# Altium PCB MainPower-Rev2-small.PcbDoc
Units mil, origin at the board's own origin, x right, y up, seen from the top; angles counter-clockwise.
Board outline 9000 x 9000 mil, 4 copper layers (Top Layer, Internal Plane 1, Internal Plane 2, Bottom Layer); 45 components, 21 nets, 446 pads, 0 vias.
Unrouted connection lines stored in the file: 206.
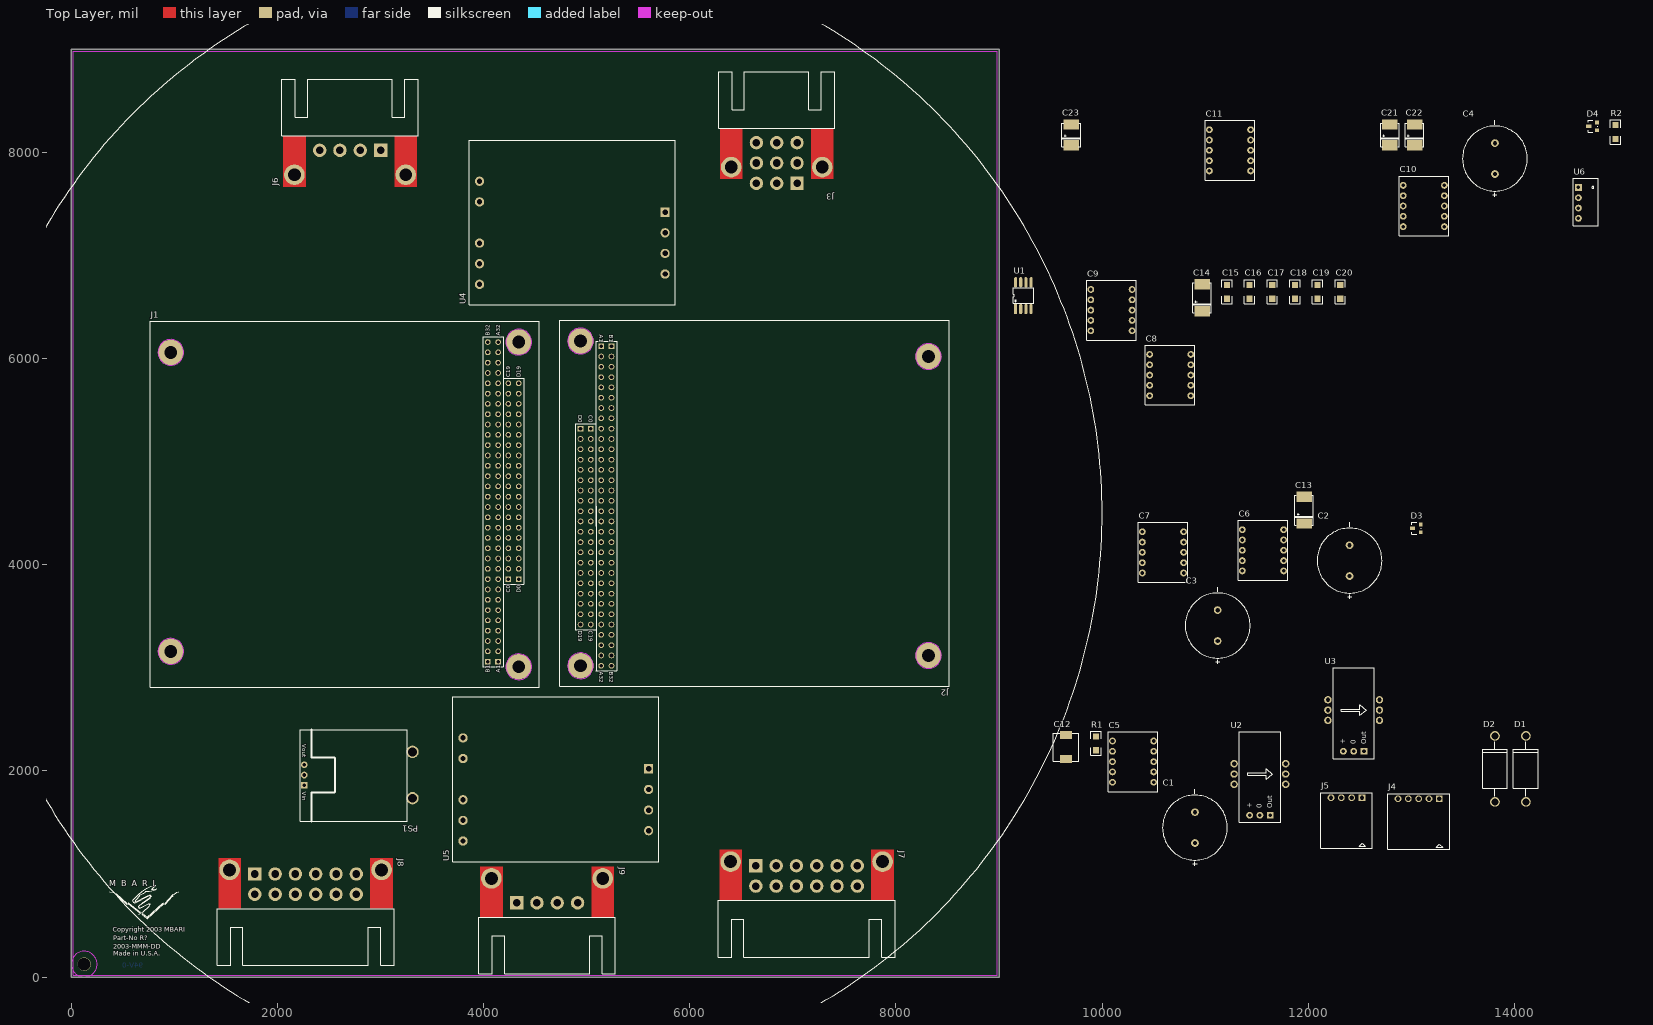
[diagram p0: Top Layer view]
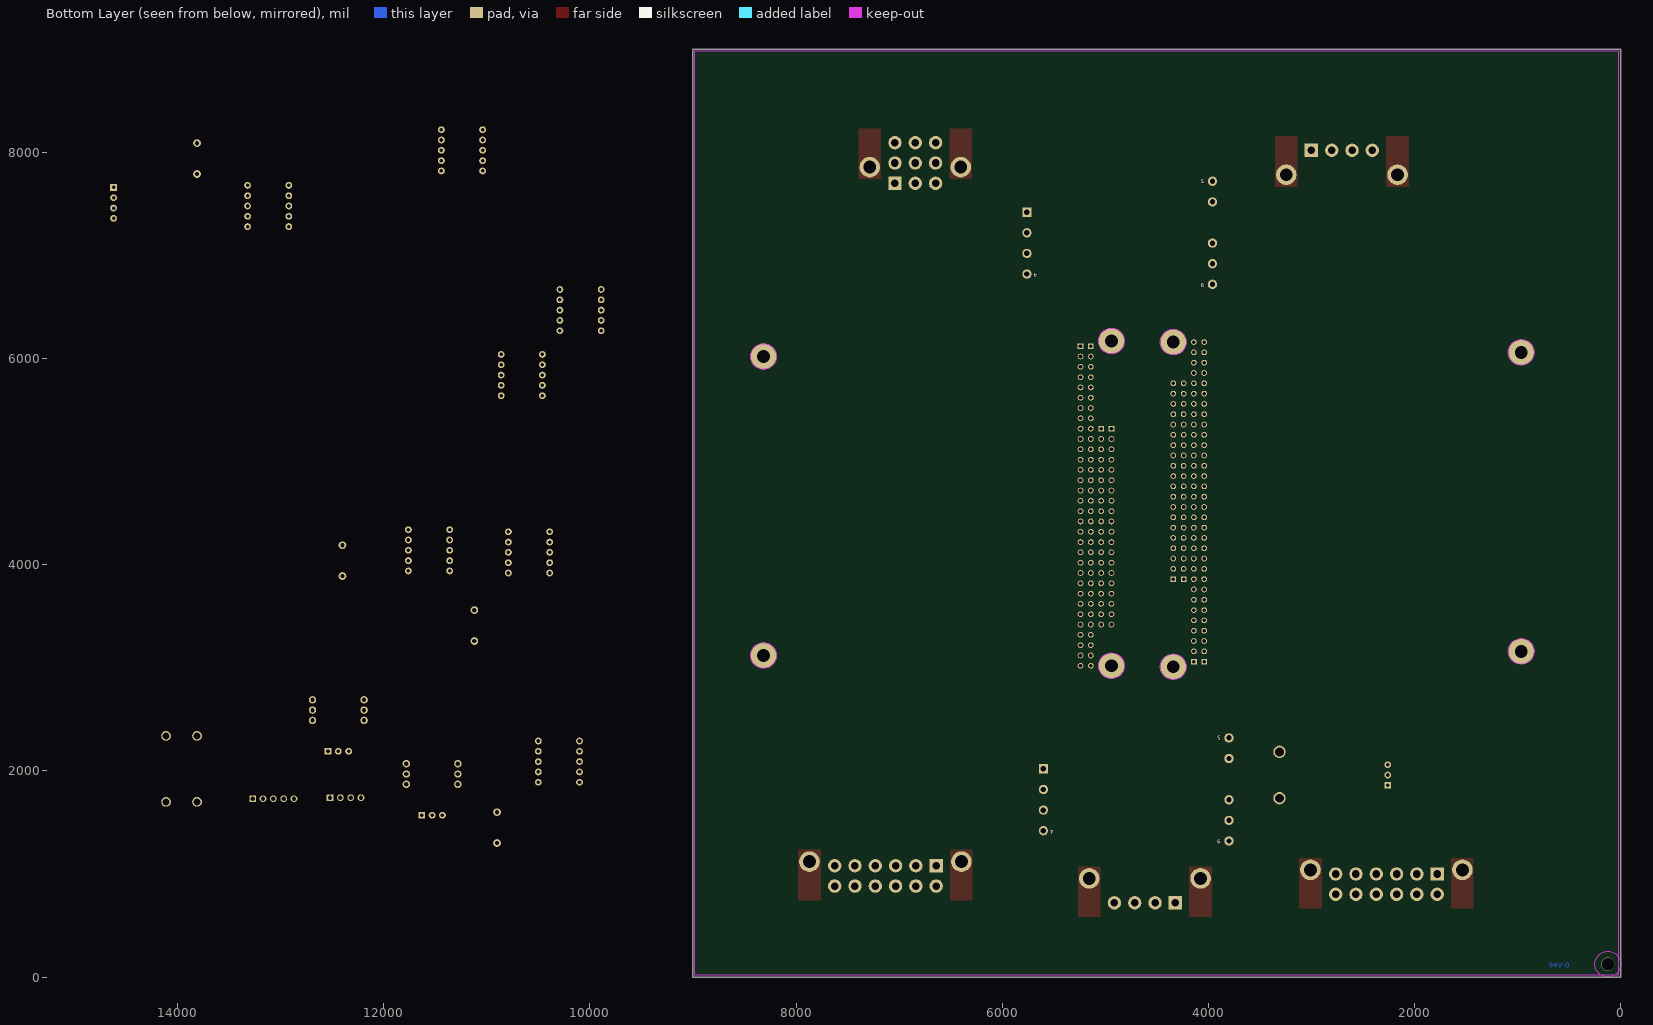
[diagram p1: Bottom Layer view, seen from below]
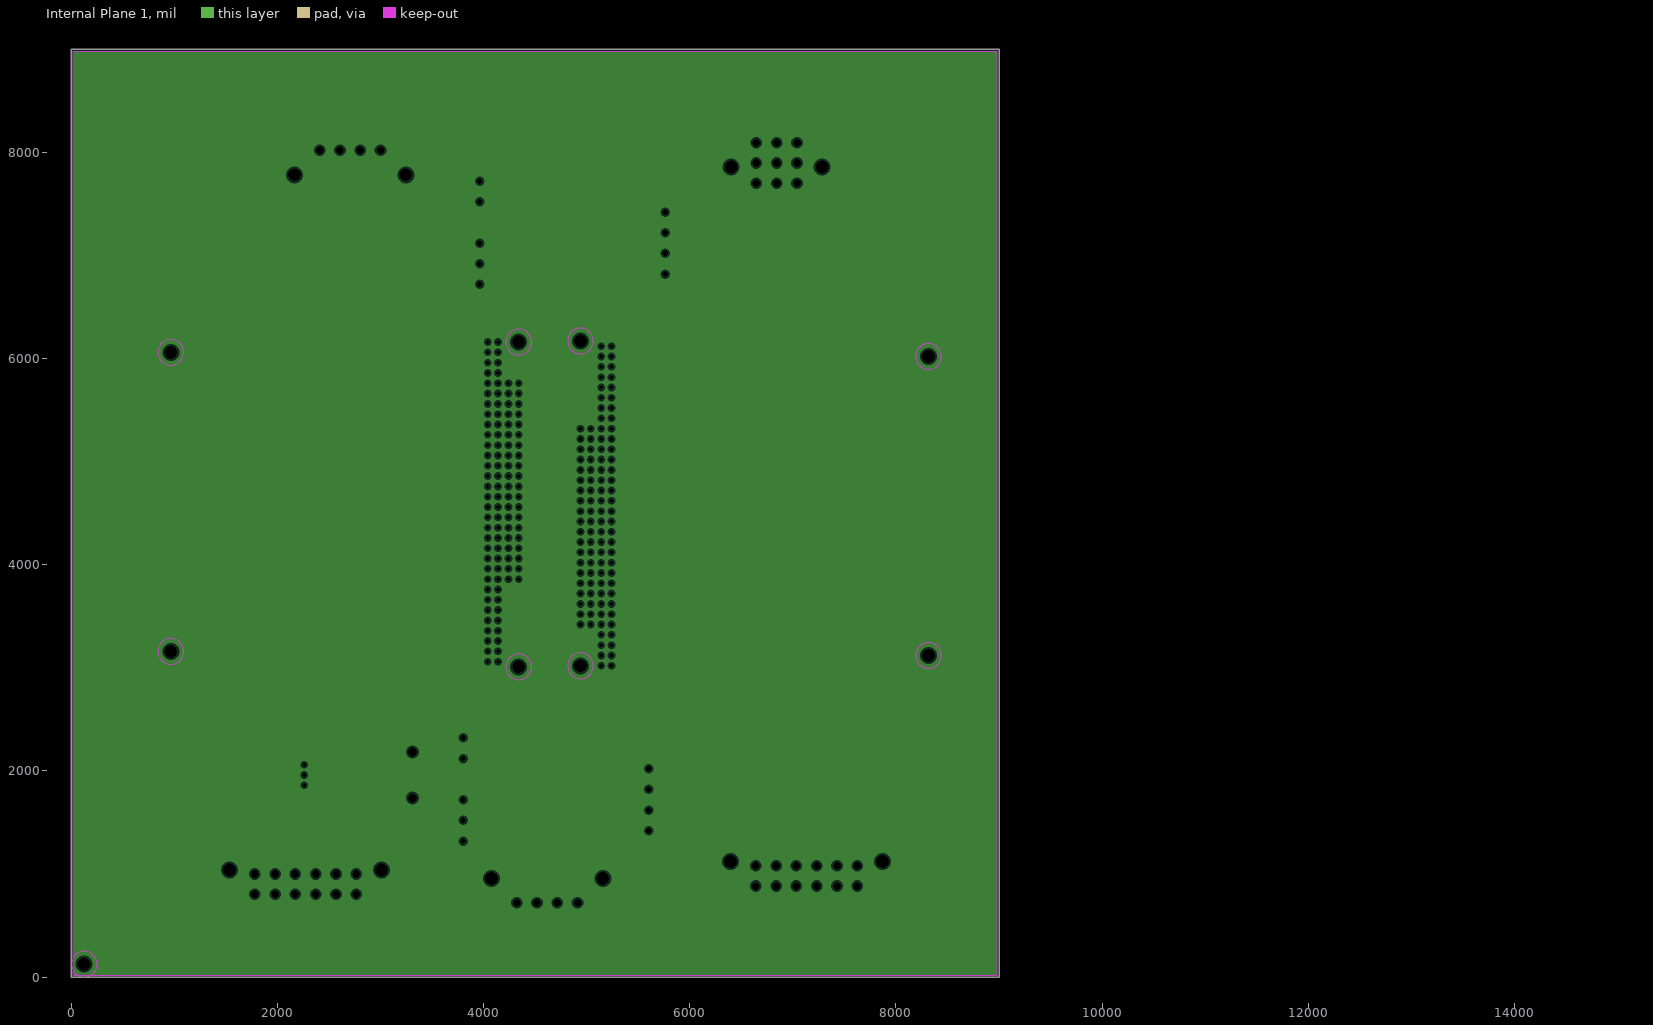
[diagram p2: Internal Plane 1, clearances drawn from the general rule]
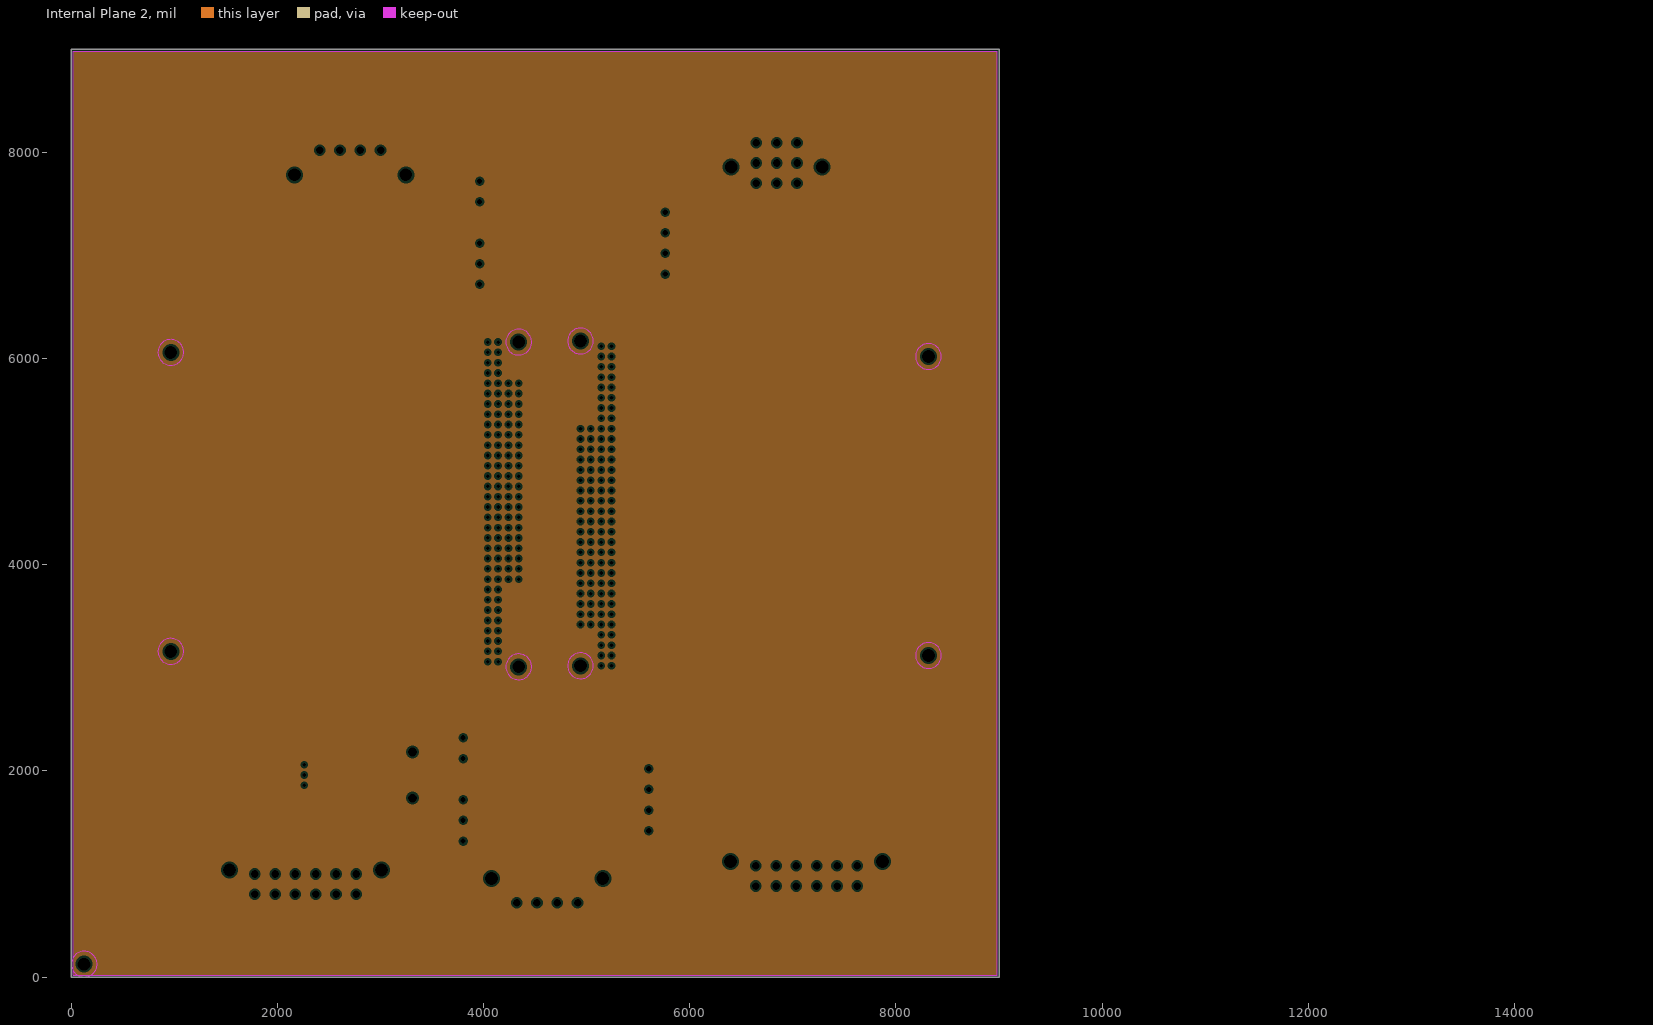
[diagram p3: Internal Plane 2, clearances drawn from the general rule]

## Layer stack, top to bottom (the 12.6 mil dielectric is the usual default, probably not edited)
Top Layer: signal copper 1.4
Dielectric: dielectric 12.6, FR-4, Dk 4.8
Internal Plane 1: plane copper 1.4
Dielectric: dielectric 12.6, FR-4, Dk 4.8
Internal Plane 2: plane copper 1.4
Dielectric: dielectric 12.6, FR-4, Dk 4.8
Bottom Layer: signal copper 1.4

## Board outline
0,0 0,9000 9000,9000 9000,0

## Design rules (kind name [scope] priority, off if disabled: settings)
Clearance [All] p1: gap=13
ComponentClearance [All] p1: gap=10 collisioncheckmode=0
FanoutControl Fanout_Small [(CompPinCount < 5)] p1: bgadir=Out bgaviamode=Centered fanoutstyle=Auto fanoutdirection=OutThenIn viagrid=1 // Fanout_Small (Default Rule)
FanoutControl Fanout_Default [All] p2: bgadir=Out bgaviamode=Centered fanoutstyle=Auto fanoutdirection=Alternating viagrid=1 // Fanout_Default (Default Rule)
FanoutControl Fanout_BGA [IsBGA] p4: bgadir=Out bgaviamode=Centered fanoutstyle=Auto fanoutdirection=Alternating viagrid=1 // Fanout_BGA (Default Rule)
FanoutControl Fanout_LCC [IsLCC] p5: bgadir=Out bgaviamode=Centered fanoutstyle=Auto fanoutdirection=Alternating viagrid=1 // Fanout_LCC (Default Rule)
HoleSize [All] p1: absolutevalues=TRUE maxlimit=152 minlimit=1 maxpercent=80.000 minpercent=20.000
PlaneClearance [All] p1: clearance=20
PlaneConnect [All] p1: planeconnectstyle=Relief reliefexpansion=20 reliefentries=4 reliefconductorwidth=10 reliefairgap=10
PolygonConnect [All] p1: connectstyle=Relief reliefconductorwidth=10 reliefentries=4 polygonreliefangle="90 Angle"
RoutingLayers [All] p1: top layer=Horizontal bottom layer=Vertical
RoutingVias [All] p1: holewidth=35 width=52 viastyle="Through Hole" minholewidth=28 minwidth=32 maxholewidth=86 maxwidth=72
SolderMaskExpansion [All] p1: expansion=4
TestPointUsage [All] p1: valid=0 allowmultiple=FALSE
Testpoint [All] p1: side=15 testpointundercomponent=TRUE minsize=40 maxsize=100 preferedsize=60 minholesize=0 maxholesize=40 preferedholesize=32 testpointgrid=1 style=1023 order=1234567890
Width [All] p1: maxlimit=250 minlimit=8 preferedwidth=12 toplayer_prefwidth=10 bottomlayer_prefwidth=10 minimp=50.000000 maximp=50.000000 favimp=50.000000
9 further rules are at their usual default settings.

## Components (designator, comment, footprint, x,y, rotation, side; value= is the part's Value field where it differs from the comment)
C1 "1000uF" RAD0.3L_0.63D 10900,1300 r90 top
C2 "1000uF" RAD0.3L_0.63D 12400,3890 r90 top
C3 "1000uF" RAD0.3L_0.63D 11120,3260 r90 top
C4 "1000uF" RAD0.3L_0.63D 13810,7790 r90 top
C5 "10uF" CAPSTICK-CS4-5 10100,1890 r90 top
C6 "10uF" CAPSTICK-CS4-5 11360,3940 r90 top
C7 "10uF" CAPSTICK-CS4-5 10390,3920 r90 top
C8 "10uF" CAPSTICK-CS4-5 10460,5640 r90 top
C9 "10uF" CAPSTICK-CS4-5 9890,6270 r90 top
C10 "10uF" CAPSTICK-CS4-5 12920,7280 r90 top
C11 "10uF" CAPSTICK-CS4-5 11040,7820 r90 top
C12 "100pF,2kV" ECK 9630,2110 r90 top
C13 "150uF,10V" 7343pol 11960,4400 r90 top
C14 "47uF,16V" 7343pol 10970,6460 r90 top
C15 "0.1uF" 1206 11210,6580 r90 top
C16 "0.1uF" 1206 11430,6580 r90 top
C17 "0.1uF" 1206 11650,6580 r90 top
C18 "0.1uF" 1206 11870,6580 r90 top
C19 "0.1uF" 1206 12090,6580 r90 top
C20 "0.1uF" 1206 12310,6580 r90 top
C21 "33uF,16V" 6032pol 12790,8070 r90 top
C22 "33uF,16V" 6032pol 13030,8070 r90 top
C23 "33uF,16V" 6032pol 9700,8070 r90 top
D1 "1N5365B" DO-201AD 14110,1700 r90 top
D2 "1N5401" DO-201AD 13810,1700 r90 top
D3 "5V LED" SOT-23 13090,4390 r90 top
D4 "12V LED" SOT-23 14800,8290 r90 top
J1 "PC104-CPU" PC104-ABCD 4140,3060 r90 top
J2 "PC104-AUX" PC104-ABCD 5140,6120 r270 top
J3 "Raw Bus In/Out" PLC09-RA 7040,7700 r180 top
J4 "Temp" CGRID5-RA 13270,1730 r0 top
J5 "CurSense" CGRID4-RA 12520,1740 r0 top
J6 "5V Power" PLA04-RA 3000,8020 r180 top
J7 "12V POWER" PLB12-RA 6640,1080 r0 top
J8 "Raw Bus Power" PLB12-RA 1780,1000 r0 top
J9 "Kearfott/ParoSci" PLA04-RA 4320,720 r0 top
PS1 "78ST133HC" PT78ST-HORIZ 2260,1960 r270 top
R1 "3.3K" 1206 9940,2200 r90 top
R2 "10K" 1206 14980,8130 r90 top
U1 "DS1620S" SOIC-8 9160,6480 r90 top
U2 "LTS6-NP" LTS6-NP 11330,1500 r90 top
U3 "LTS6-NP" LTS6-NP 12240,2120 r90 top
U4 "UHE-5/5000-Q12" DATEL-UHE 5760,7420 r180 top
U5 "UHE-12/2500-D24" DATEL-UHE 5600,2020 r180 top
U6 "NKE1209S" NKEDCDC 14620,7660 r0 top

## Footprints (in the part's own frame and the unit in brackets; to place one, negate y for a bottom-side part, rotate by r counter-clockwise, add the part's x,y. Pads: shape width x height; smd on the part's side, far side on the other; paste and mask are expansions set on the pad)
1206 [mil]
  rect 60x60 smd: 1(0,0) 2(135,0)
  silkscreen extent -50,-50 185,50
6032pol [mil]
  rect 100x150 smd: 1(0,0) 2(200,0)
  silkscreen extent -15,-90 215,90
7343pol [mil]
  rect 100x150 smd: 1(0,0) 2(260,0)
  silkscreen extent -15,-90 275,90
CAPSTICK-CS4-5 [mil]
  round 66 hole 35: 1(0,0) 1(100,0) 1(200,0) 1(300,0) 1(400,0) 2(0,-400) 2(100,-400) 2(200,-400) 2(300,-400) 2(400,-400)
  silkscreen extent -90,-440 490,40
CGRID4-RA [mil]
  rect 66x66 hole 42: 1(0,0)
  round 66 hole 42: 2(-100,0) 3(-200,0) 4(-300,0)
  silkscreen extent -400,-490 100,50
CGRID5-RA [mil]
  rect 66x66 hole 42: 1(0,0)
  round 66 hole 42: 2(-100,0) 3(-200,0) 4(-300,0) 5(-400,0)
  silkscreen extent -500,-490 100,50
DATEL-UHE [mil] "Datel UHE 1.6x2.0 DC/DC Converter"
  rect 90x90 hole 52: 1(0,0)
  round 90 hole 52: 2(0,200) 3(0,400) 4(0,600) 5(1800,-300) 6(1800,-100) 7(1800,300) 8(1800,500) 9(1800,700)
  silkscreen extent -100,-700 1900,900
DO-201AD [mil]
  round 95 hole 67: 1(0,0) 2(640,0)
  silkscreen extent 55,-120 585,120
ECK [mm]
  rect 2x3 smd: 1(0.15,-0.5) 2(6.075,-0.475)
  silkscreen extent -0.4,-3.6 6.5,2.7
LTS6-NP [mil]
  round 72 hole 42: 1(370,-450) 2(470,-450) 3(570,-450) 4(570,50) 5(470,50) 6(370,50)
  rect 66x66 hole 35: a(70,-300)
  round 66 hole 35: b(70,-200) c(70,-100)
  silkscreen extent 0,-400 880,0
NKEDCDC [mil]
  rect 66x66 hole 35: 1(0,0)
  round 66 hole 35: 2(0,-100) 3(0,-200) 4(0,-300)
  silkscreen extent -50,-370 190,90
PC104-ABCD [mil] "PC104 Outline and ABCD Rails"
  round 250 hole 125: 0(-50,-200) 0(100,3175) 0(3000,3175) 0(3100,-200)
  rect 55x55 hole 35: A1(0,0) B1(0,100) C0(800,-100) D0(800,-200)
  round 55 hole 35: A2(100,0) A3(200,0) A4(300,0) A5(400,0) A6(500,0) A7(600,0) A8(700,0) A9(800,0) A10(900,0) A11(1000,0) A12(1100,0) A13(1200,0) A14(1300,0) A15(1400,0) A16(1500,0) A17(1600,0) A18(1700,0) A19(1800,0) A20(1900,0) A21(2000,0) A22(2100,0) A23(2200,0) A24(2300,0) A25(2400,0) A26(2500,0) A27(2600,0) A28(2700,0) A29(2800,0) A30(2900,0) A31(3000,0) A32(3100,0) B2(100,100) B3(200,100) B4(300,100) B5(400,100) B6(500,100) B7(600,100) B8(700,100) B9(800,100) B10(900,100) B11(1000,100) B12(1100,100) B13(1200,100) B14(1300,100) B15(1400,100) B16(1500,100) B17(1600,100) B18(1700,100) B19(1800,100) B20(1900,100) B21(2000,100) B22(2100,100) B23(2200,100) B24(2300,100) B25(2400,100) B26(2500,100) B27(2600,100) B28(2700,100) B29(2800,100) B30(2900,100) B31(3000,100) B32(3100,100) C1(900,-100) C2(1000,-100) C3(1100,-100) C4(1200,-100) C5(1300,-100) C6(1400,-100) C7(1500,-100) C8(1600,-100) C9(1700,-100) C10(1800,-100) C11(1900,-100) C12(2000,-100) C13(2100,-100) C14(2200,-100) C15(2300,-100) C16(2400,-100) C17(2500,-100) C18(2600,-100) C19(2700,-100) D1(900,-200) D2(1000,-200) D3(1100,-200) D4(1200,-200) D5(1300,-200) D6(1400,-200) D7(1500,-200) D8(1600,-200) D9(1700,-200) D10(1800,-200) D11(1900,-200) D12(2000,-200) D13(2100,-200) D14(2200,-200) D15(2300,-200) D16(2400,-200) D17(2500,-200) D18(2600,-200) D19(2700,-200)
  Keep-Out Layer circle w10: c3100,-200 r125
  Keep-Out Layer circle w10: c3000,3175 r125
  Keep-Out Layer circle w10: c100,3175 r125
  Keep-Out Layer circle w10: c-50,-200 r125
  silkscreen extent -250,-400 3300,3375
PLA04-RA [mil]
  round 200 hole 125: 0(-244.5,237) 0(835.5,237)
  rect 130x130 hole 73: 1(0,0)
  round 130 hole 73: 2(197,0) 3(394,0) 4(591,0)
  Top Layer region: -354.5,-138 -134.5,-138 -134.5,354 -354.5,354
  Top Layer region: 725.5,-138 945.5,-138 945.5,354 725.5,354
  silkscreen extent -366,-690 959,-140
PLB12-RA [mil]
  round 200 hole 125: 0(-244.5,40) 0(1229.5,40)
  rect 130x130 hole 73: 1(0,0)
  round 130 hole 73: 2(197,0) 3(394,0) 4(591,0) 5(788,0) 6(985,0) 7(0,-197) 8(197,-197) 9(394,-197) 10(591,-197) 11(788,-197) 12(985,-197)
  Top Layer region: -354.5,-335 -134.5,-335 -134.5,157 -354.5,157
  Top Layer region: 1119.5,-335 1339.5,-335 1339.5,157 1119.5,157
  silkscreen extent -366,-887 1352,-337
PLC09-RA [mil]
  round 200 hole 125: 0(-244.5,-157) 0(638.5,-157)
  rect 130x130 hole 73: 1(0,0)
  round 130 hole 73: 2(197,0) 3(394,0) 4(0,-197) 5(197,-197) 6(394,-197) 7(0,-394) 8(197,-394) 9(394,-394)
  Top Layer region: -354.5,-532 -134.5,-532 -134.5,-40 -354.5,-40
  Top Layer region: 528.5,-532 748.5,-532 748.5,-40 528.5,-40
  silkscreen extent -365,-1084 761,-534
PT78ST-HORIZ [mil]
  round 120 hole 86: 0(-225,1050) 0(225,1050)
  rect 65x65 hole 35: 1(100,0)
  round 65 hole 35: 2(0,0) 3(-100,0)
  silkscreen extent -440,-40 450,1000
RAD0.3L_0.63D [mil]
  round 75 hole 42: 1(0,0) 2(300,0)
  silkscreen extent -220,-315 520,315
SOIC-8 [mil]
  rect 100x30 smd: 1(0,0)
  oval 100x30 smd: 2(0,-50) 3(0,-100) 4(0,-150) 5(260,-150) 6(260,-100) 7(260,-50) 8(260,0)
  silkscreen extent 55,-175 205,25
SOT-23 [mil]
  rect 36x36 smd: 1(0,0) 2(-75,0)
  rect 36x50 smd: 3(-37,80)
  silkscreen extent -95,-5 20,85

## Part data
C1 C2 C3 C4: library part "CAPACITOR POL", "Capacitor"
C5 C6 C7 C8 C9 C10 C11 C12 C13 C14 C15 C16 C17 C18 C19 C20 C21 C22 C23: library part CAPACITOR, "Capacitor"
D1: library part ZENER3, "Zener Diode"
D2: library part DIODE_S, "Diode"
D3 D4: library part LED, "LED"
J1 J2: library part PC104-ABCD, "PC104 ABCD Rails"
J3: library part CON3X3, "9 pin connector"
J4: library part CON5, "Connector"
J5 J6 J9: library part CON4, "Connector"
J7 J8: library part CON12-PLB, "Positronic 12 pin connector"
PS1: library part PT78STXXX, "Power Trends Switching Reg"
R1 R2: library part RESISTOR, "Resistor"
U1: library part DS1620, "DallasSemi Digital Thermometer and Thermostat"
U2 U3: "Current Transducer"
U4 U5: library part UHE, "Datel UHE DC->DC Isolated Converter"
U6: library part NKE1209S-BW, "DC->DC Isol Converter 12->9VDC"

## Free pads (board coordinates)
  round 130 hole 125: 0(125,125)

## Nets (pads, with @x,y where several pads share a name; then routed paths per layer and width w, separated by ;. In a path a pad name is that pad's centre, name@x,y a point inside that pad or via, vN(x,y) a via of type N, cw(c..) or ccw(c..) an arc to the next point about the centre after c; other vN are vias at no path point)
5V: C13.1 C15.1 C16.1 C17.1 C18.1 C19.1 C20.1 J1.B3 J1.B29 J1.D16 J2.B3 J2.B29 J2.D16 J6.1 J6.3 R1.1 U4.5 U4.6
9V: C21.1 J9.3 U6.4
9VGND: C21.2 J9.4 U6.3
12V: C14.1 C22.1 C23.1 J7.1 J7.2 J7.3 J7.4 J7.5 J7.6 PS1.1 R2.1 U5.5 U5.6 U6.2
AN0VJ3: J5.4 U2.b U3.b
AN5VJ3: J5.1 U2.c U3.c
BUS+: D1.2 D2.2 J3.1 J3.2 U2.4 U2.5 U2.6 U3.4 U3.5 U3.6
BUS-: C1.2 C2.2 C3.2 C4.2 C5.2 C6.2 C7.2 C8.2 C9.2 C10.2 C11.2 C12.2 D1.1 D2.1 J3.4 J3.5 J3.6 J8.7 J8.8 J8.9 J8.10 J8.11 J8.12 J9.2 U4.2 U5.2
ELEC+: C2.1 C3.1 C4.1 C6.1 C7.1 C8.1 C9.1 C10.1 C11.1 J8.1 J8.2 J8.3 J8.4 J8.5 J8.6 J9.1 U3.1 U3.2 U3.3 U4.1 U5.1
ELECCUR: J5.3 U3.a
GND: C13.2 C14.2 C15.2 C16.2 C17.2 C18.2 C19.2 C20.2 C22.2 C23.2 D3.3 D4.3 J1.A32 J1.B1 J1.B31 J1.B32 J1.C0 J1.D0 J1.D18 J1.D19 J2.A32 J2.B1 J2.B31 J2.B32 J2.C0 J2.D0 J2.D18 J2.D19 J6.2 J6.4 J7.7 J7.8 J7.9 J7.10 J7.11 J7.12 PS1.2 U4.7 U4.8 U5.7 U5.8 U6.1
LOCO+: C1.1 C5.1 J3.3 U2.1 U2.2 U2.3
LOCOCUR: J5.2 U2.a
NetD3_2: D3.2 R1.2
NetD4_2: D4.2 R2.2
NetJ4_1: J4.1 U1.4
NetJ4_2: J4.2 U1.8
NetJ4_3: J4.3 U1.1
NetJ4_4: J4.4 U1.2
NetJ4_5: J4.5 U1.3
SHIELD: C12.1 J3.7 J3.8 J3.9
pads on no net: D3.1 D4.1 J1.0 J1.A1 J1.A2 J1.A3 J1.A4 J1.A5 J1.A6 J1.A7 J1.A8 J1.A9 J1.A10 J1.A11 J1.A12 J1.A13 J1.A14 J1.A15 J1.A16 J1.A17 J1.A18 J1.A19 J1.A20 J1.A21 J1.A22 J1.A23 J1.A24 J1.A25 J1.A26 J1.A27 J1.A28 J1.A29 J1.A30 J1.A31 J1.B2 J1.B4 J1.B5 J1.B6 J1.B7 J1.B8 J1.B9 J1.B10 J1.B11 J1.B12 J1.B13 J1.B14 J1.B15 J1.B16 J1.B17 J1.B18 J1.B19 J1.B20 J1.B21 J1.B22 J1.B23 J1.B24 J1.B25 J1.B26 J1.B27 J1.B28 J1.B30 J1.C1 J1.C2 J1.C3 J1.C4 J1.C5 J1.C6 J1.C7 J1.C8 J1.C9 J1.C10 J1.C11 J1.C12 J1.C13 J1.C14 J1.C15 J1.C16 J1.C17 J1.C18 J1.C19 J1.D1 J1.D2 J1.D3 J1.D4 J1.D5 J1.D6 J1.D7 J1.D8 J1.D9 J1.D10 J1.D11 J1.D12 J1.D13 J1.D14 J1.D15 J1.D17 J2.0 J2.A1 J2.A2 J2.A3 J2.A4 J2.A5 J2.A6 J2.A7 J2.A8 J2.A9 J2.A10 J2.A11 J2.A12 J2.A13 J2.A14 J2.A15 J2.A16 J2.A17 J2.A18 J2.A19 J2.A20 J2.A21 J2.A22 J2.A23 J2.A24 J2.A25 J2.A26 J2.A27 J2.A28 J2.A29 J2.A30 J2.A31 J2.B2 J2.B4 J2.B5 J2.B6 J2.B7 J2.B8 J2.B9 J2.B10 J2.B11 J2.B12 J2.B13 J2.B14 J2.B15 J2.B16 J2.B17 J2.B18 J2.B19 J2.B20 J2.B21 J2.B22 J2.B23 J2.B24 J2.B25 J2.B26 J2.B27 J2.B28 J2.B30 J2.C1 J2.C2 J2.C3 J2.C4 J2.C5 J2.C6 J2.C7 J2.C8 J2.C9 J2.C10 J2.C11 J2.C12 J2.C13 J2.C14 J2.C15 J2.C16 J2.C17 J2.C18 J2.C19 J2.D1 J2.D2 J2.D3 J2.D4 J2.D5 J2.D6 J2.D7 J2.D8 J2.D9 J2.D10 J2.D11 J2.D12 J2.D13 J2.D14 J2.D15 J2.D17 J3.0 J6.0 J7.0 J8.0 J9.0 PS1.0 PS1.3 U1.5 U1.6 U1.7 U4.3 U4.4 U4.9 U5.3 U5.4 U5.9

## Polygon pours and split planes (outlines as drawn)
no net on Internal Plane 1 (split plane): 20.01,20.01 20.01,8979.99 8979.99,8979.99 8979.99,20.01
no net on Internal Plane 2 (split plane): 20.01,20.01 20.01,8979.99 8979.99,8979.99 8979.99,20.01

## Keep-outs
Keep-Out Layer:
  circle w10: c125,125 r125
  lines w10: 20,20 8980,20 8980,8980 20,8980 20,20
  text ".GKO" at 15240,-540 h90

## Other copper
Top Layer:
  text ".GTL" at 15240,-540 h90
Bottom Layer:
  text "94V-0" at 697.07,88.79 h50
  text ".GBL" at 15240,-540 h90

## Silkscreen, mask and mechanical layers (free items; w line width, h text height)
Top Overlay:
  circle w10: c4500,4500 r5500
  lines w10: 373,826 405,824 436,806 537,715 550,719 557,718 671,631 ; 428,808 531,711 ; 536,708 551,712 666,624 ; 653,608 699,635 758,689 761,696 761,706 759,709 753,710 746,710 ; 684,610 731,573 ; 688,617 736,579 888,717 897,721 911,716 990,802 993,797 1022,823 1042,827 ; 760,695 760,703 758,707 753,709 746,710 ; 894,713 909,708 ; 916,712 981,785 ; 984,782 990,791 ; 746,710 739,707 696,687 679,676 656,672 652,677 653,689 691,721 759,768 770,784 766,795 760,797 736,791 700,771 652,743 622,733 618,737 629,752 647,767 669,797 687,807 702,814 715,822 722,833 757,833 780,838 796,844 812,849 829,859 824,855 795,850 778,850 821,889 772,881 733,863 690,835 651,801 623,774 601,749 597,741 596,735 599,728 604,724 612,719 622,720 750,790 760,793 767,793 771,791 773,787 775,782 772,775 764,766 669,701 658,693 654,685 653,679 657,672 664,670 672,672 746,710 ; 737,568 896,713 737,568
  text "M  B  A  R  I" at 370,880 h55
  text "Copyright 2003 MBARI" at 400,440 h45
  text "Part-No R?" at 405,356.68 h45
  text "2003-MMM-DD" at 405,276.68 h45
  text "Made in U.S.A." at 405,206.68 h45
  text ".GTO" at 15240,-540 h90
Bottom Overlay:
  text ".GBO" at 15250,-540 h90
Top Solder:
  text ".GTS" at 15240,-540 h90
Bottom Solder:
  text ".GBS" at 15240,-540 h90
Drill Guide:
  text ".GG1" at 15450,-540 h90
Mechanical 4:
  the board outline again, w10
Mechanical 16:
  lines w5: -800,1750 -600,1750 ; -800,4500 -600,4500 ; -800,7250 -600,7250 ; 2035,-800 2035,-600 ; 2035,9600 2035,9795 ; 4865,-800 4865,-600 ; 4865,9600 4865,9795 ; 7700,-800 7700,-600 ; 7700,9600 7700,9795 ; 9700,0 15600,0 ; 10530,-800 10530,-600 ; 10530,9600 10530,9795 ; 11100,-300 15600,-300 ; 11100,300 12600,300 ; 12600,-600 12600,0 12600,600 ; 13365,-800 13365,-600 ; 13365,9600 13365,9795 ; 14700,-600 14700,0 ; 15600,1750 15795,1750 ; 15600,4500 15795,4500 ; 15600,7250 15795,7250 ; 11100,-600 9700,-600 9700,600 11100,600 ; 11100,-600 15600,-600 ; 11100,-600 11100,600 ; 11100,600 12600,600 ; 12600,600 15600,600 15600,-600 ; 15600,-600 -600,-600 -600,9600 15600,9600 15600,-600 ; -800,-800 -800,9795 15795,9795 15795,-800 -800,-800
  lines w10: 10033,446 10065,444 10096,426 10197,335 10210,339 10217,338 10331,251 ; 10088,428 10191,331 ; 10196,328 10211,332 10326,244 ; 10313,228 10359,255 10418,309 10421,316 10421,326 10419,329 10413,330 10406,330 ; 10344,230 10391,193 ; 10348,237 10396,199 10548,337 10557,341 10571,336 10650,422 10653,417 10682,443 10702,447 ; 10420,315 10420,323 10418,327 10413,329 10406,330 ; 10554,333 10569,328 ; 10576,332 10641,405 ; 10644,402 10650,411 ; 10406,330 10399,327 10356,307 10339,296 10316,292 10312,297 10313,309 10351,341 10419,388 10430,404 10426,415 10420,417 10396,411 10360,391 10312,363 10282,353 10278,357 10289,372 10307,387 10329,417 10347,427 10362,434 10375,442 10382,453 10417,453 10440,458 10456,464 10472,469 10489,479 10484,475 10455,470 10438,470 10481,509 10432,501 10393,483 10350,455 10311,421 10283,394 10261,369 10257,361 10256,355 10259,348 10264,344 10272,339 10282,340 10410,410 10420,413 10427,413 10431,411 10433,407 10435,402 10432,395 10424,386 10329,321 10318,313 10314,305 10313,299 10317,292 10324,290 10332,292 10406,330 ; 10397,188 10556,333 10397,188
  text "1" at 601.34,9665 h70
  text "2" at 3427,9665 h70
  text "3" at 6252,9665 h70
  text "4" at 9093.01,9665 h70
  text "5" at 11927,9665 h70
  text "6" at 14762,9665 h70
  text "A" at -725,8622 h70
  text "A" at 15675,8622 h70
  text "B" at -725,5888.02 h70
  text "B" at 15675,5888.02 h70
  text "C" at -725,3107 h70
  text "C" at 15675,3107 h70
  text "M  B  A  R  I" at 10030,500 h55
  text "ENGINEER:" at 11150,500 h45
  text "TITLE:" at 12650,500 h45
  text "Mark Sibenac" at 11660,470 h70
  text "Title I" at 13000,380 h90
  text "1 831 775 2028" at 11650,330 h60
  text "D" at -725,285 h70
  text "D" at 15675,285 h70
  text "PCB DESIGNER:" at 11150,205 h45
  text "Title II" at 13020,160 h90
  text "Copyright      2003" at 9880,150 h60
  text "Monterey Bay Aquarium Research Institute" at 9750,40 h45
  text "DATE:" at 11150,-100 h45
  text "PART NO.:" at 12650,-100 h45
  text "REV:" at 14750,-100 h45
  text ".PRINT_DATE" at 11200,-220 h70
  text "1" at 15030,-220 h90
  text "Part Number" at 13010,-230 h60
  text "M.B.A.R.I." at 9780,-240 h100
  text "7700 Sandholdt Rd." at 9770,-340 h60
  text "FILE NAME:" at 11150,-400 h45
  text "DWG NO:" at 12650,-400 h45
  text "GERBER:" at 14750,-400 h45
  text "Moss Landing, CA 95039" at 9770,-450 h60
  text "DWG Number" at 13010,-490 h60
  text ".PCB_FILE_NAME_NO_PATH" at 11200,-520 h70
  text ".GM16" at 14860,-530 h70
  text "Fax: 1 831 775 1646" at 9770,-550 h60
  text "1" at 601.34,-735 h70
  text "2" at 3427,-735 h70
  text "3" at 6252,-735 h70
  text "4" at 9093.01,-735 h70
  text "5" at 11927,-735 h70
  text "6" at 14762,-735 h70
Drill Drawing:
  text ".LEGEND" at 9945,870 h60
  text "Drill Drawing." at 9925,780 h60
  text ".GD1" at 15445,-540 h90

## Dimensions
0,0 to 9000,0 on Mechanical 4
0,9000 to 0,0 on Mechanical 4
125,125 to 0,0 on Mechanical 4
125,125 to 0,0 on Mechanical 4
